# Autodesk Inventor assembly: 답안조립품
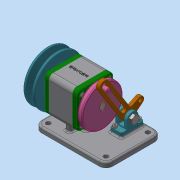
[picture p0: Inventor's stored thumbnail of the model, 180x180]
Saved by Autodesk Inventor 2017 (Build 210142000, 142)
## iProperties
Part Number: 답안조립품
Material: 일반
Document SubType Name: Assembly
Designer: mrc
Mass: 1532.4 g
Surface Area: 1486.39 cm^2
Volume: 469.453 cm^3
Density: 3.26422 g/cm^3
Author: mrc
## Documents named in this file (19)
- C:\Users\mrc\Desktop\601106V1040\답안조립품.iam
- C:\Users\mrc\Desktop\601106V1040\본체.ipt
- C:\Users\mrc\Desktop\601106V1040\V-벨트풀리.ipt
- C:\Users\mrc\Desktop\601106V1040\너트 M8.ipt
- C:\Users\mrc\Desktop\601106V1040\너트 M10x1.ipt
- C:\Users\mrc\Desktop\601106V1040\돌림판.ipt
- C:\Users\mrc\Desktop\601106V1040\멈춤나사 M3x5.ipt
- C:\Users\mrc\Desktop\601106V1040\베어링 6004.ipt
- C:\Users\mrc\Desktop\601106V1040\볼트 M4.ipt
- C:\Users\mrc\Desktop\601106V1040\오일 실 17 30 5.ipt
- C:\Users\mrc\Desktop\601106V1040\와셔 8x15.5.ipt
- C:\Users\mrc\Desktop\601106V1040\축.ipt
- C:\Users\mrc\Desktop\601106V1040\커버.ipt
- C:\Users\mrc\Desktop\601106V1040\크랭크.ipt
- C:\Users\mrc\Desktop\601106V1040\키 4 x 4 x 8.ipt
- C:\Users\mrc\Desktop\601106V1040\키 5 x 5 x 12.ipt
- C:\Users\mrc\Desktop\601106V1040\핀 3 x 8.ipt
- C:\Users\mrc\Desktop\601106V1040\힌지 축.ipt
- C:\Users\mrc\Desktop\601106V1040\힌지.ipt
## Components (3 placed, 2 different names)
1. V-벨트풀리:1
2. 핀 3 x 8:1 — 플러쉬:1
3. 핀 3 x 8:2 — 플러쉬:2
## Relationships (2: Flush 2)
- 플러쉬:1 [Flush]: 핀 3 x 8:1
- 플러쉬:2 [Flush]: 핀 3 x 8:2
